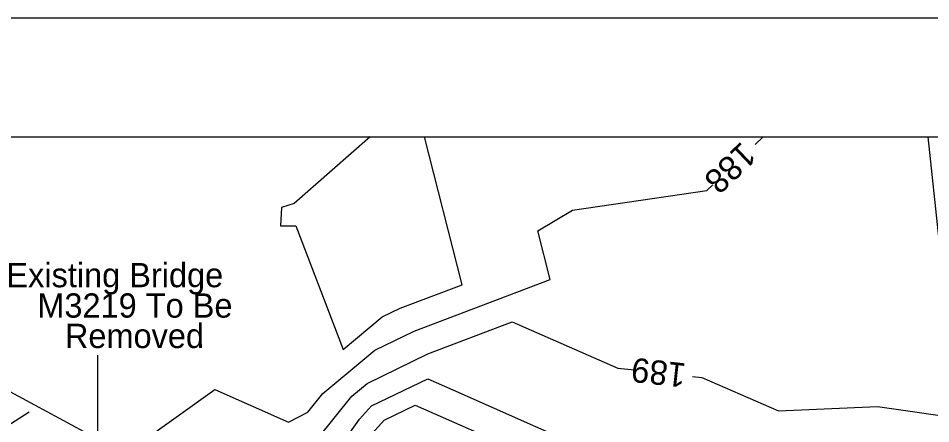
# Model space of a CAD drawing. Extents: x 1385284 to 1385995, y 1975154 to 1975620.
# Drawn here: x 1385581.7 to 1385675.6, y 1975577.9 to 1975619.6 of the extents above; entities that cross this region are included whole.
import ezdxf

# ---------------------------------------------------------------- set-up
doc = ezdxf.new("R2010")
doc.units = 0
for name, color, linetype in [('1', 7, 'Continuous'), ('Default', 7, 'Continuous'), ('DTM CONTOURS_MAJOR', 7, 'Continuous'), ('DTM_CONTOURS_MINOR', 7, 'Continuous'), ('R_Prop Surface', 7, 'Continuous'), ('S_BRIDGE', 7, 'Continuous')]:
    doc.layers.add(name, color=color, linetype=linetype)

msp = doc.modelspace()

# ---------------------------------------------------------------- linework, layer by layer
at = {"layer": '1'}
msp.add_line((1385315.54, 1975607.406), (1385982.69, 1975607.406), dxfattribs=at)
for points in [[(1385994.751, 1975619.62), (1385283.842, 1975619.62), (1385283.842, 1975153.738), (1385994.751, 1975153.738)], [(1385315.54, 1975165.953), (1385315.54, 1975607.406), (1385810.692, 1975607.406), (1385810.692, 1975586.483), (1385892.572, 1975586.483), (1385892.572, 1975580.3), (1385982.69, 1975580.3), (1385982.69, 1975165.953)]]:
    msp.add_lwpolyline(points, close=True, dxfattribs=at)
at = {"layer": 'Default'}
msp.add_line((1385589.922, 1975575.352), (1385589.922, 1975584.945), dxfattribs=at)
at = {"layer": 'DTM CONTOURS_MAJOR'}
msp.add_lwpolyline([(1385598.965, 1975548.409), (1385601.11, 1975552.38), (1385601.119, 1975552.409), (1385601.122, 1975552.415), (1385601.13, 1975552.429), (1385607.72, 1975567.96), (1385609.941, 1975569.1), (1385613.03, 1975572.943), (1385616.842, 1975578.357), (1385618.07, 1975579.723), (1385623.879, 1975582.507), (1385626.447, 1975581.381), (1385643.433, 1975573.823), (1385646.003, 1975572.698), (1385662.883, 1975565.183), (1385667.001, 1975563.078), (1385675.033, 1975559.172)], dxfattribs=at)
at = {"layer": 'DTM_CONTOURS_MINOR'}
for points in [[(1385617.947, 1975607.406), (1385610.114, 1975600.54), (1385608.806, 1975600.135), (1385608.722, 1975598.252), (1385610.29, 1975598.251), (1385615.159, 1975585.508)], [(1385615.159, 1975585.508), (1385619.191, 1975588.87), (1385621.034, 1975589.768), (1385627.401, 1975592.188), (1385623.528, 1975607.406)], [(1385651.095, 1975582.747), (1385652.048, 1975582.64), (1385659.929, 1975579.196), (1385670.133, 1975579.656), (1385679.685, 1975578.269), (1385678.412, 1975583.481), (1385682.928, 1975587.999), (1385679.153, 1975593.933), (1385676.458, 1975596.79), (1385675.316, 1975607.406)], [(1385657.533, 1975606.609), (1385658.373, 1975607.406)], [(1385577.055, 1975538.851), (1385583.12, 1975547.386), (1385583.722, 1975549.277), (1385585.943, 1975553.127), (1385589.489, 1975561.152), (1385591.914, 1975569.855), (1385594.007, 1975575.712), (1385601.977, 1975581.384), (1385609.546, 1975578.052), (1385611.528, 1975579.069), (1385613.078, 1975580.998), (1385618.408, 1975585.443), (1385622.459, 1975587.415), (1385636.452, 1975592.735), (1385635.182, 1975597.722), (1385638.747, 1975599.876), (1385652.572, 1975601.899), (1385653.182, 1975602.478)], [(1385562.866, 1975481.018), (1385563.716, 1975498.339), (1385566.287, 1975500.31), (1385572.546, 1975503.642), (1385585.482, 1975508.711), (1385572.018, 1975516.132), (1385577.884, 1975524.056), (1385581.986, 1975529.59), (1385586.864, 1975537.76), (1385589.378, 1975541.298), (1385592.421, 1975550.843), (1385595.925, 1975556.919), (1385603.651, 1975570.298), (1385603.747, 1975570.566), (1385603.842, 1975570.633), (1385603.931, 1975570.594), (1385610.734, 1975574.084), (1385616.057, 1975580.707), (1385617.625, 1975582.015), (1385623.884, 1975585.062), (1385632.559, 1975588.36), (1385643.399, 1975583.605), (1385645.132, 1975583.412)], [(1385617.369, 1975492.225), (1385607.301, 1975499.112), (1385606.759, 1975506.204), (1385597.926, 1975513.203), (1385593.044, 1975520.782), (1385590.045, 1975523.554), (1385593.409, 1975532.864), (1385594.84, 1975537.505), (1385595.303, 1975538.903), (1385601.683, 1975550.713), (1385601.762, 1975550.79), (1385602.065, 1975551.447), (1385602.382, 1975552.155), (1385602.612, 1975552.619), (1385602.984, 1975553.423), (1385609.856, 1975566.014), (1385610.538, 1975566.429), (1385610.608, 1975566.793), (1385616.058, 1975574.533), (1385619.393, 1975578.242), (1385622.579, 1975579.77), (1385630.039, 1975576.498), (1385630.815, 1975576.153)]]:
    msp.add_lwpolyline(points, dxfattribs=at)
at = {"layer": 'R_Prop Surface'}
msp.add_line((1385557.699, 1975562.925), (1385582.859, 1975579.112), dxfattribs=at)
at = {"layer": 'S_BRIDGE'}
msp.add_line((1385552.739, 1975596.41), (1385613.262, 1975563.695), dxfattribs=at)

# ---------------------------------------------------------------- texts
at = {"layer": 'Default'}
for s, rotation, p in [('188', 223.50962, (1385656.147, 1975607.016)), ('189', 173.63149, (1385650.513, 1975584.069))]:
    msp.add_text(s, height=2.5, rotation=rotation, dxfattribs=at).set_placement(p)
for s, height, p in [('Existing Bridge', 2.49999, (1385580.53, 1975591.928)), ('M3219 To Be ', 2.49999, (1385583.711, 1975588.798)), ('Removed', 2.5, (1385586.546, 1975585.668))]:
    msp.add_text(s, height=height, dxfattribs=at).set_placement(p)

doc.saveas('drawing.dxf')
